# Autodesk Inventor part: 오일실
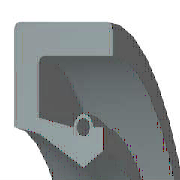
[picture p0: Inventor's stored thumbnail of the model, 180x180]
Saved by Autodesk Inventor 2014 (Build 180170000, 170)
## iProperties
IsCustomPart: 1
Created: 2015-10
Part Number: 오일실
Material: 고무
Description: 오일-실
Document SubType Name: Modeling
Standard: KS B 2804
Designer: mdu
Standards Organization: KS
Language: ko-KR
Size Designation: S - 25 38 8
Categories: <MemberInstance><Categories><Category DisplayName="샤프트 부품" InternalName="7f7aeb1f-a693-4053-b835-cee3144e0d98" Mnemonic="SHFT"><Category DisplayName="실링" Intern
Density: 0.93 g/cm^3
Appearance: 고무 - 검은색 - 버전 1.1
Author: mdu
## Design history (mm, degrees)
revolve "본체" stored, may be unused: angle "d17" = 90 deg
revolve "스프링1" stored, may be unused: angle "d18" = 90 deg
body "Solid1"
sketch "스케치1"
  geometry: L1 (0, 19)-(8, 19); L2 (8, 19)-(8, 17.75); L3 (8, 17.75)-(1.75, 17.75); L4 (0, 19)-(0, 14.6); L5 (0, 14.6)-(1.75, 14.25); L6 (1.75, 14.25)-(4.9, 12.5); L7 (4.9, 12.5)-(0, 12.5); L8 (6.3, 13.375)-(6.3, 14.6); L9 (0, 0)-(9.586, 0) reference; L10 (4.9, 12.5)-(6.3, 13.375); L11 (0, 18)-(0, -3) reference; L12 (-1.917, 0)-(11.503, 0) reference; L13 (4.2, 14.6)-(1.75, 15.09); L14 (1.75, 15.09)-(1.75, 17.75); L15 (6.3, 14.6)-(5.6, 14.6); C1 r 0.455 at (4.9, 14.6); A1 r 0.7 centre (4.9, 14.6) between (5.6, 14.6) and (4.2, 14.6)
  constraints: 26 end point, 5 horizontal alignment, 4 perpendicular, 2 centre point, 2 collinear, 2 horizontal, 2 parallel, 2 point on circle, 2 point on line, 2 vertical alignment, 1 coincident
  dimensions: "d0" = 38 diameter of L1 L9 (= SD2); "d1" = 26.75 diameter of L8.start L9 (= ABDM); "d2" = 1.25 distance of L1.end L2.end (computed from SD); "d3" = 0.91 diameter of C1 (= SPDI); "d4" = 1.4 diameter of A1 (= SPDA); "d5" = 25 diameter of L6.end L9 (= NND); "d6" = 28.5 diameter of L5.end L9 (= TKDM); "d7" = 29.2 diameter of L4.end L9 (= HLDM); "d8" = 4.9 distance from line of C1.centre L4 (= SPDST); "d9" = 6.3 distance between parallel lines of L8 L4 (= SDI); "d10" = 8 distance between parallel lines of L2 L4 (= SWDT); "d12" = 1.75 distance between parallel lines of L14 L4 (= SD)
fillet "모깎기1" dims "d11" = 0.3 (= RR)
other parameters: "SD2" = 38 [user parameter; used in 1 equation term], "SWDT" = 8 [user parameter; used in 1 equation term], "RR" = 0.3 [user parameter; used in 1 equation term], "SD" = 1.75 [user parameter; used in 2 equation terms], "NND" = 25 [user parameter; used in 1 equation term], "SPDA" = 1.4 [user parameter; used in 1 equation term], "SPDI" = 0.91 [user parameter; used in 1 equation term], "TKDM" = 28.5 [user parameter; used in 1 equation term], "HLDM" = 29.2 [user parameter; used in 1 equation term], "ABDM" = 26.75 [user parameter; used in 1 equation term], "SDI" = 6.3 [user parameter; used in 1 equation term], "SPDST" = 4.9 [user parameter; used in 1 equation term], "d13" = 0, "d14" = 0, "d15" = 0, "LAB" = 0.35 [user parameter]
